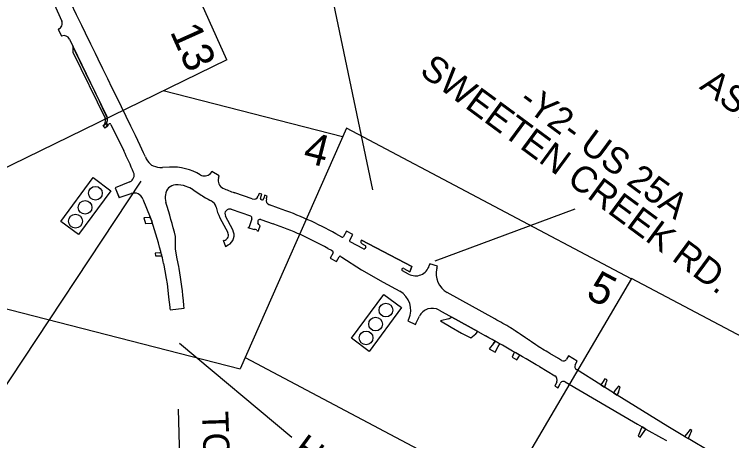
# Model space of a CAD drawing. Extents: x 945666 to 965748, y 644452 to 663300.
# Drawn here: x 951483 to 954496, y 654307 to 656097 of the extents above; entities that cross this region are included whole.
import ezdxf

# ---------------------------------------------------------------- set-up
doc = ezdxf.new("R2010")
doc.units = 0
for name, color, linetype in [('Old_Level_23', 7, 'Continuous'), ('Prop EOT', 7, 'Continuous'), ('Prop PHM Traffic Signal CELL', 7, 'Continuous'), ('Prop Shade Light', 7, 'Continuous'), ('Sheet Plan Layout CELL', 7, 'Continuous')]:
    doc.layers.add(name, color=color, linetype=linetype)

msp = doc.modelspace()

# ---------------------------------------------------------------- linework, layer by layer
at = {"layer": 'Old_Level_23'}
for p, q in [((952752.1, 656484.8), (952987.9, 655359.8)), ((951372.5, 654425.5), (952015.2, 655396.2)), ((953837.5, 655278.9), (953248.6, 655060.3)), ((952647.9, 654320.5), (952176.9, 654715.4)), ((952170.9, 654438.9), (952196.4, 653446.7))]:
    msp.add_line(p, q, dxfattribs=at)
at = {"layer": 'Prop EOT'}
for p, q in [((951906, 655368.1), (951922.9, 655327.4)), ((952049, 655244.5), (952053.8, 655246.1)), ((952058.1, 655220.5), (952063.5, 655220.5)), ((952094.4, 655095.6), (952099.3, 655096.6)), ((952097.6, 655082.8), (952102.8, 655082.8)), ((953308.3, 654818.3), (953321, 654825.6)), ((953421, 654755.8), (953430.3, 654765)), ((953494.8, 654714.8), (953502, 654725.1)), ((953515.7, 654703), (953521.7, 654714)), ((953578.6, 654667.3), (953583.9, 654678.7)), ((953599.2, 654655.5), (953605.6, 654666.2)), ((953952.8, 654552.1), (953946.2, 654541.5)), ((953966.4, 654543.6), (953961.8, 654531.7)), ((954006.3, 654518.8), (953998.9, 654508.7)), ((954019.9, 654510.3), (954015.3, 654498.4)), ((954113.8, 654353.8), (954119.5, 654364.9)), ((954127.8, 654345.9), (954135.3, 654356)), ((954306, 654334.6), (954298, 654324.8)), ((954318.9, 654327), (954313.3, 654315.9))]:
    msp.add_line(p, q, dxfattribs=at)
msp.add_lwpolyline([(952940.5, 655149), (953153.1, 655038), (953144.2, 655016.3)], dxfattribs=at)
at = {"layer": 'Prop PHM Traffic Signal CELL'}
for p, q in [((951678.6, 655227.4), (951814.6, 655411.7)), ((951814.6, 655411.7), (951889, 655356.8)), ((951889, 655356.8), (951753.1, 655172.5)), ((951753.1, 655172.5), (951678.6, 655227.4)), ((952898.9, 654737.1), (953034.8, 654921.4)), ((953034.8, 654921.4), (953109.3, 654866.5)), ((953109.3, 654866.5), (952973.4, 654682.2)), ((952973.4, 654682.2), (952898.9, 654737.1))]:
    msp.add_line(p, q, dxfattribs=at)
for centre in [(951823.6, 655345.9), (951780.1, 655286.9), (951739.9, 655228.8), (953043.8, 654855.6), (953000.3, 654796.6), (952960.1, 654738.5)]:
    msp.add_circle(centre, 28.8, dxfattribs=at)
at = {"layer": 'Prop Shade Light'}
for p, q in [((951636, 656171.9), (951682, 656068.9)), ((951668.7, 656035.6), (951667, 656035)), ((951667, 656035), (951681.8, 656006)), ((951715.4, 655992.5), (951729.6, 655960.5)), ((951728.4, 655962.9), (951729.3, 655938)), ((951729.6, 655960.5), (951802.9, 655809.7)), ((951729.3, 655938), (951864, 655660.9)), ((951802.9, 655809.7), (951871.4, 655667.9)), ((951865.4, 655657.3), (951873.9, 655661.4)), ((951873.9, 655661.4), (951865.4, 655657.3)), ((951874.3, 655659.5), (951873.9, 655661.4)), ((951856, 655629.5), (951863.6, 655619.9)), ((951868.4, 655638.9), (951877.5, 655631.8)), ((951874.5, 655634.1), (951868.4, 655638.9)), ((951877.3, 655632), (951874.5, 655634.1)), ((951888.8, 655635.1), (951942.5, 655524.6)), ((952135.3, 655456), (952104.7, 655454.5)), ((952312.8, 655438), (952306.2, 655429)), ((952343.3, 655419), (952312.8, 655438)), ((952340.6, 655409.5), (952343.3, 655419)), ((951967.8, 655393.8), (951906, 655368.1)), ((951906, 655368.1), (951922.9, 655327.5)), ((951922.9, 655327.5), (951973.1, 655344.8)), ((952234.5, 655359.7), (952262, 655341.9)), ((952511.7, 655345.3), (952508.7, 655337.8)), ((952522.2, 655341.7), (952511.7, 655345.3)), ((952508.7, 655337.8), (952507.4, 655334.2)), ((952516.2, 655324.5), (952519.5, 655334)), ((952523.6, 655317.7), (952518.7, 655319.4)), ((952519.5, 655334), (952522.2, 655341.7)), ((952531.6, 655329.8), (952528.7, 655320.3)), ((952534, 655337.6), (952531.6, 655329.8)), ((952545, 655333.7), (952534, 655337.6)), ((952541.6, 655322.2), (952542.7, 655325.9)), ((952542.7, 655325.9), (952545, 655333.7)), ((952592.8, 655283.6), (952554, 655297.1)), ((952394, 655278.6), (952474.3, 655250.7)), ((952049, 655244.6), (952026.8, 655242.7)), ((952026.8, 655242.7), (952034.5, 655219)), ((952053.8, 655246.1), (952049, 655244.6)), ((952060.6, 655229.2), (952053.8, 655246.1)), ((952346.4, 655243.3), (952379.4, 655180.7)), ((952400.6, 655191.9), (952369.8, 655250.3)), ((952480.5, 655238.1), (952469.8, 655205.7)), ((952518.5, 655235.3), (952569.8, 655217.5)), ((952034.5, 655219), (952058.1, 655220.5)), ((952058.1, 655220.5), (952063.5, 655220.5)), ((952463.4, 655202.5), (952489.7, 655193.4)), ((952510, 655214.2), (952506.3, 655221.3)), ((952507.7, 655187.1), (952513.9, 655204.9)), ((952513.9, 655204.9), (952515.5, 655209.4)), ((952159.5, 655111.9), (952159.5, 655164.1)), ((952501.4, 655189.3), (952507.7, 655187.1)), ((952858.7, 655162.1), (952833.8, 655175.9)), ((952878.4, 655187.2), (952865.5, 655164)), ((952904.6, 655172.7), (952878.4, 655187.2)), ((952891.8, 655149.5), (952904.6, 655172.7)), ((952360.7, 655149.5), (952369.2, 655121.9)), ((952948.9, 655112.1), (952893.7, 655142.7)), ((952940.5, 655149), (952939.6, 655147)), ((952943.7, 655133.9), (952956.9, 655126.6)), ((952167.5, 655071), (952159.5, 655111.9)), ((952369.2, 655121.9), (952381.7, 655128.8)), ((952799.9, 655114.7), (952814.7, 655106.5)), ((952814.7, 655106.5), (952820.5, 655102.6)), ((952958.8, 655119.8), (952955.7, 655114)), ((952094.4, 655095.6), (952074.4, 655094.9)), ((952074.4, 655094.9), (952076.4, 655083.4)), ((952076.4, 655083.4), (952097.6, 655082.8)), ((952099.3, 655096.6), (952094.4, 655095.6)), ((952097.6, 655082.8), (952102.8, 655082.8)), ((952102.8, 655082.8), (952102.8, 655082.8)), ((952822.1, 655096), (952809.4, 655073.9)), ((952809.4, 655073.9), (952835.4, 655059)), ((952835.4, 655059), (952847, 655079)), ((952854.1, 655080.7), (952858.1, 655078)), ((952858.1, 655078), (952940.5, 655024.1)), ((952173.4, 655038.5), (952167.5, 655071)), ((953227.8, 655049.9), (953225.5, 655042.2)), ((953260.4, 655040.4), (953227.8, 655049.9)), ((952940.5, 655024.1), (953032.1, 654973.3)), ((953138.9, 655006.7), (953113, 655021)), ((953118.4, 655030.6), (953144.2, 655016.3)), ((953257.9, 655030.9), (953260.4, 655040.4)), ((953032.1, 654973.3), (953101.5, 654934.8)), ((953500.9, 654818.5), (953301.2, 654929.2)), ((952137, 654856.8), (952196.8, 654862.9)), ((953139.1, 654817.4), (953135.7, 654810.1)), ((953135.7, 654810.1), (953167.4, 654795.1)), ((953167.4, 654795.1), (953170.9, 654802.5)), ((953170.9, 654802.5), (953184.3, 654829.6)), ((953308.3, 654818.4), (953272.6, 654810.2)), ((953272.6, 654810.2), (953318.3, 654783.6)), ((953321, 654825.6), (953308.3, 654818.4)), ((953430.3, 654765), (953321, 654825.6)), ((953318.3, 654783.6), (953361.3, 654758)), ((953361.3, 654758), (953400.5, 654739.1)), ((953400.5, 654739.1), (953421, 654755.9)), ((953421, 654755.9), (953430.3, 654765)), ((953494.8, 654714.8), (953476.6, 654692.6)), ((953502, 654725.1), (953494.8, 654714.8)), ((953515.7, 654703), (953521.7, 654714)), ((953476.6, 654692.6), (953502, 654678.3)), ((953502, 654678.3), (953515.7, 654703)), ((953578.6, 654667.3), (953573.4, 654657.9)), ((953573.4, 654657.9), (953594, 654646.1)), ((953583.8, 654678.7), (953578.6, 654667.3)), ((953594, 654646.1), (953599.2, 654655.5)), ((953599.2, 654655.5), (953605.6, 654666.3)), ((953732.5, 654673.3), (953723.9, 654678.3)), ((953769.1, 654651.8), (953732.5, 654673.3)), ((953781.6, 654644), (953769.1, 654651.8)), ((953810.3, 654662.9), (953802.5, 654649.3)), ((953846.4, 654640.5), (953810.3, 654662.9)), ((953838.3, 654625.2), (953846.4, 654640.5)), ((953688.4, 654618), (953753, 654580)), ((953963.3, 654566.6), (953952.8, 654552.1)), ((953972.8, 654562.8), (953963.3, 654566.6)), ((953966.4, 654543.7), (953972.8, 654562.8)), ((953761.2, 654554.7), (953753, 654536.3)), ((953753, 654536.3), (953760.4, 654533)), ((953760.4, 654533), (953767.7, 654529.8)), ((953767.7, 654529.8), (953775.4, 654547.4)), ((953796.8, 654554.3), (954099.9, 654375.9)), ((953952.8, 654552.1), (953946.2, 654541.5)), ((953946.2, 654541.5), (953961.8, 654531.8)), ((953961.8, 654531.8), (953966.4, 654543.7)), ((954020.8, 654536.7), (954006.3, 654518.8)), ((954019.9, 654510.3), (954027.7, 654533.7)), ((954027.7, 654533.7), (954020.8, 654536.7)), ((954006.3, 654518.8), (953998.9, 654508.7)), ((953998.9, 654508.7), (954015.3, 654498.5)), ((954015.3, 654498.5), (954019.9, 654510.3)), ((954099.9, 654375.9), (954119.5, 654364.9)), ((954113.8, 654353.8), (954102.7, 654326.5)), ((954119.5, 654364.9), (954113.8, 654353.8)), ((954135.3, 654356.1), (954119.5, 654364.9)), ((954127.8, 654346), (954135.3, 654356.1)), ((954102.7, 654326.5), (954110.9, 654321.7)), ((954110.9, 654321.7), (954127.8, 654346)), ((954306, 654334.7), (954298, 654324.8)), ((954298, 654324.8), (954313.3, 654315.9)), ((954313.3, 654315.9), (954318.9, 654327.1))]:
    msp.add_line(p, q, dxfattribs=at)
for points in [[(951781.9, 656018), (951766.2, 656050.3), (951744.2, 656095.3), (951720.1, 656145.4), (951681.2, 656224.3), (951657.7, 656273), (951645.7, 656297.5)], [(951823.7, 655932.1), (951804.5, 655971.9), (951781.9, 656018)], [(951759.5, 655898.7), (951743.2, 655932.2), (951732.3, 655954.6), (951729.6, 655960.5), (951728.4, 655962.9)], [(952033.3, 655498.4), (952025.7, 655515.1), (952010.9, 655546.9), (951991.5, 655587.8), (951972.1, 655627.3), (951952.5, 655667.7), (951932.7, 655709.3), (951913, 655748.8), (951894.4, 655786.8), (951875.1, 655826.5), (951855, 655867.7), (951835, 655908.9), (951823.7, 655932.1)], [(951802.9, 655809.7), (951783.1, 655850.3), (951778.9, 655858.9), (951777.5, 655861.7), (951773.2, 655870.4), (951759.5, 655898.7)], [(951871.4, 655667.9), (951869.1, 655672.7), (951859.4, 655692.7), (951840.3, 655732.3), (951820.7, 655772.9), (951802.9, 655809.7)], [(951867.3, 655623.3), (951867.5, 655623)], [(951867.5, 655623), (951872.7, 655627.1), (951875.5, 655629.7), (951877.3, 655632)], [(951868.4, 655638.9), (951868.4, 655638.9)], [(952482, 655322.1), (952408.8, 655347.5), (952408.8, 655347.5), (952407.6, 655347.9)], [(952407.6, 655347.9), (952407.6, 655347.9)], [(952023.2, 655321.9), (952053.8, 655246.1), (952060.6, 655229.2)], [(952063.5, 655220.5), (952063.5, 655220.5)], [(952463.4, 655202.5), (952463.4, 655202.5)], [(953144.2, 655016.3), (953153.1, 655038), (952940.5, 655149)], [(952102.8, 655082.8), (952102.8, 655082.8)], [(952110.1, 655051.4), (952111.4, 655044.7), (952115.7, 655020.7), (952120.9, 654988.8)], [(952193.4, 654895.2), (952191, 654916.6), (952188.8, 654935.7), (952186.5, 654954.1), (952180.9, 654993.5), (952174.8, 655030.6), (952173.4, 655038.5)], [(952120.9, 654988.8), (952124.3, 654965.4), (952127.4, 654939.5), (952131.2, 654910.1), (952133.6, 654888.2), (952135.8, 654868.4), (952136, 654865.3), (952136.5, 654862.1), (952137, 654856.8)], [(952196.8, 654862.9), (952195.5, 654875.3), (952193.4, 654895.2)], [(953267.1, 654855.5), (953321, 654825.6), (953430.3, 654765), (953461.6, 654747.6)], [(954227.6, 654366.3), (954015.3, 654498.5), (953998.9, 654508.7), (953961.8, 654531.8), (953946.2, 654541.5), (953843.6, 654605.4)], [(954119.5, 654364.9), (954135.3, 654356.1), (954200.8, 654319.4), (954222.3, 654307.4)], [(954623.6, 654133.3), (954421.9, 654252), (954406.4, 654261.1), (954313.3, 654315.9), (954298, 654324.8), (954227.6, 654366.3)], [(954318.9, 654327.1), (954328.7, 654349.5), (954321.3, 654353.6), (954306, 654334.7)]]:
    msp.add_lwpolyline(points, dxfattribs=at)
for centre, radius, start, end in [((951659.2, 656058.7), 25, 292.3217, 24.0909), ((951691.6, 655981.9), 26, 23.9453, 112.1499), ((951841.5, 655649.9), 25, 305.3243, 17.1428), ((951841.5, 655649.9), 25, 17.1428, 25.9325), ((951849.3, 655655.6), 25.3, 318.8171, 29.3178), ((951849.3, 655655.6), 25.3, 29.2276, 29.3178), ((951849.3, 655655.6), 25.3, 345.2315, 8.9433), ((951840.1, 655649.2), 37.6, 308.6221, 336.2991), ((951840.1, 655649.2), 37.6, 316.3257, 336.2991), ((951849.3, 655655.6), 25.3, 318.8171, 319.781), ((951844.6, 655657.3), 41.6, 322.3103, 328.4923), ((951884.3, 655632.9), 5, 25.9327, 148.4923), ((950261.8, 654707.3), 1868.9, 22.8539, 25.9327), ((952124.2, 655540), 100, 204.5323, 225.3117), ((952078.5, 655493.8), 35, 225.3117, 249.0253), ((952101.8, 655554.4), 100, 249.0253, 271.6452), ((952144.8, 655221.2), 235, 59.5369, 92.3285), ((951956.3, 655421.5), 30, 292.54, 22.8539), ((952281.7, 655453.9), 35, 239.5369, 314.5158), ((952374.1, 655399.4), 35, 163.226, 244.7668), ((952162.3, 655336.2), 45, 93.002, 175.1414), ((952166.2, 655261.3), 120, 71.3136, 93.002), ((952144.8, 655221.2), 165, 57.0814, 68.7466), ((951986.1, 655306.9), 40, 21.9932, 108.9966), ((952574.4, 655824.6), 505, 244.7668, 250.713), ((952237, 655329.8), 120, 175.1414, 190.5694), ((952574.4, 655824.6), 575, 237.0814, 242.5873), ((952488.6, 655341), 20, 250.85, 340.2328), ((952520, 655323.2), 4, 160.9125, 250.85), ((952524.9, 655321.5), 4, 250.85, 342.8101), ((952560.6, 655316), 20, 161.7571, 250.85), ((950261.8, 654707.3), 1951.9, 13.536, 17.9187), ((952291.3, 655278.6), 40, 12.2235, 62.5873), ((952498.5, 655323.5), 172, 192.2235, 207.8093), ((952387.5, 655259.7), 20, 70.85, 207.8093), ((952089.3, 653833.6), 1535, 60.9833, 70.85), ((950283, 654638.4), 1873.2, 13.723, 18.3831), ((950283, 654638.4), 1873.2, 18.1036, 18.3831), ((952471, 655241.2), 10, 341.7238, 70.85), ((952515.2, 655225.9), 10, 70.85, 207.4729), ((952465.1, 655207.2), 5, 250.7829, 341.7238), ((952493.9, 655186.6), 8, 19.776, 121.924), ((952518.8, 655218.9), 10, 207.4729, 250.4692), ((952089.3, 653833.6), 1465, 60.9833, 70.85), ((952359, 655170), 23, 293.3287, 27.8093), ((952359, 655170), 47, 298.8358, 27.8093), ((952861.1, 655166.5), 5, 240.9833, 330.8246), ((952365, 655156.2), 8, 237.4086, 293.3287), ((952896.1, 655147.1), 5, 150.9833, 240.9833), ((952948.5, 655142.6), 10, 154.0037, 240.9833), ((952951.3, 655116.5), 5, 240.9833, 330.9833), ((952954.5, 655122.2), 5, 330.9833, 60.9833), ((950283, 654638.4), 1873.2, 13.723, 14.1587), ((950283, 654638.4), 1873.2, 12.7359, 13.7229), ((952817.8, 655098.5), 5, 329.9283, 56.7892), ((952851.3, 655076.5), 5, 56.7892, 149.9283), ((953115.7, 655025.8), 5.5, 60.9833, 240.9833), ((953168, 655059.2), 60, 240.9833, 343.6093), ((953344.9, 655007.9), 90, 165.2281, 240.9833), ((953057.9, 654856.1), 90, 334.5523, 60.9833), ((953238, 654803), 60, 60.9833, 153.6981), ((948482.4, 645771.1), 10346, 60.55899, 60.98333), ((948482.4, 645771.1), 10265, 59.525, 60.98333), ((948482.4, 645771.1), 10265, 60.5988, 60.72501), ((948482.4, 645771.1), 10335, 59.525, 59.72459), ((948482.4, 645771.1), 10265, 60.06021, 60.19995), ((953789.5, 654656.7), 15, 238.0929, 330.233), ((953851.5, 654618.1), 15, 151.8521, 238.0929), ((953742.9, 654562.8), 20, 336.1833, 59.525), ((953789.2, 654541.3), 15, 59.525, 156.1833)]:
    msp.add_arc(centre, radius, start, end, dxfattribs=at)
for points in [[(951868.6, 655639.2), (951869.5, 655640.4), (951870.3, 655641.6), (951871.7, 655644), (951872.9, 655646.5), (951873.4, 655647.8), (951873.8, 655649.1)], [(951873.9, 655661.4), (951873.2, 655663.4), (951871.4, 655667.9)], [(951856, 655629.5), (951857.6, 655630.4), (951858.4, 655630.9), (951859.2, 655631.3), (951860.3, 655631.9), (951861.4, 655632.6), (951862.4, 655633.2), (951863.5, 655634), (951864.2, 655634.5), (951864.8, 655635), (951866.1, 655636.2), (951867.2, 655637.5), (951868.4, 655638.8), (951868.4, 655638.9)], [(951868.4, 655638.9), (951868.4, 655638.8), (951867.2, 655637.5), (951866.1, 655636.2), (951864.8, 655635), (951864.2, 655634.5), (951863.5, 655634), (951862.4, 655633.2), (951861.4, 655632.6), (951860.3, 655631.9), (951859.2, 655631.3), (951858.4, 655630.9), (951857.6, 655630.4), (951856, 655629.5)], [(953581.7, 654771.8), (953581.3, 654772), (953580.8, 654772.4), (953580.2, 654772.8), (953579.6, 654773.1), (953579.1, 654773.5), (953578.5, 654773.9), (953577.9, 654774.3), (953577.4, 654774.7), (953576.8, 654775), (953576.2, 654775.4), (953575.7, 654775.8), (953575.1, 654776.2), (953574.5, 654776.5), (953574, 654776.9), (953573.4, 654777.3), (953572.8, 654777.7), (953572.3, 654778), (953571.7, 654778.4), (953571.1, 654778.8), (953570.6, 654779.2), (953570, 654779.6), (953569.4, 654779.9), (953568.9, 654780.3), (953568.3, 654780.7), (953567.7, 654781.1)], [(953595.7, 654762.4), (953595.5, 654762.6), (953594.9, 654762.9), (953594.3, 654763.3), (953593.8, 654763.7), (953593.2, 654764.1), (953592.6, 654764.5), (953592.1, 654764.8), (953591.5, 654765.2), (953590.9, 654765.6), (953590.4, 654766), (953589.8, 654766.3), (953589.3, 654766.7), (953588.7, 654767.1), (953588.1, 654767.5), (953587.6, 654767.9), (953587, 654768.2), (953586.4, 654768.6), (953585.9, 654769), (953585.3, 654769.4), (953584.7, 654769.7), (953584.2, 654770.1), (953583.6, 654770.5), (953583, 654770.9), (953582.5, 654771.3), (953581.9, 654771.6), (953581.7, 654771.8)], [(953609.6, 654753.1), (953609, 654753.5), (953608.5, 654753.8), (953607.9, 654754.2), (953607.3, 654754.6), (953606.8, 654755), (953606.2, 654755.4), (953605.6, 654755.7), (953605.1, 654756.1), (953604.5, 654756.5), (953603.9, 654756.9), (953603.4, 654757.3), (953602.8, 654757.6), (953602.3, 654758), (953601.7, 654758.4), (953601.1, 654758.8), (953600.6, 654759.2), (953600, 654759.5), (953599.4, 654759.9), (953598.9, 654760.3), (953598.3, 654760.7), (953597.7, 654761), (953597.2, 654761.4), (953596.6, 654761.8), (953596, 654762.2), (953595.7, 654762.4)], [(953623.5, 654743.7), (953623.1, 654744), (953622.6, 654744.4), (953622, 654744.7), (953621.4, 654745.1), (953620.9, 654745.5), (953620.3, 654745.9), (953619.8, 654746.3), (953619.2, 654746.6), (953618.6, 654747), (953618.1, 654747.4), (953617.5, 654747.8), (953616.9, 654748.2), (953616.4, 654748.5), (953615.8, 654748.9), (953615.2, 654749.3), (953614.7, 654749.7), (953614.1, 654750.1), (953613.5, 654750.4), (953613, 654750.8), (953612.4, 654751.2), (953611.9, 654751.6), (953611.3, 654751.9), (953610.7, 654752.3), (953610.2, 654752.7), (953609.6, 654753.1)], [(953637.4, 654734.3), (953637.2, 654734.5), (953636.7, 654734.8), (953636.1, 654735.2), (953635.5, 654735.6), (953635, 654736), (953634.4, 654736.4), (953633.9, 654736.7), (953633.3, 654737.1), (953632.7, 654737.5), (953632.2, 654737.9), (953631.6, 654738.3), (953631, 654738.6), (953630.5, 654739), (953629.9, 654739.4), (953629.3, 654739.8), (953628.8, 654740.2), (953628.2, 654740.5), (953627.7, 654740.9), (953627.1, 654741.3), (953626.5, 654741.7), (953626, 654742.1), (953625.4, 654742.5), (953624.8, 654742.8), (953624.3, 654743.2), (953623.7, 654743.6), (953623.5, 654743.7)], [(953651.3, 654724.9), (953650.7, 654725.3), (953650.2, 654725.7), (953649.6, 654726.1), (953649.1, 654726.4), (953648.5, 654726.8), (953647.9, 654727.2), (953647.4, 654727.6), (953646.8, 654728), (953646.2, 654728.4), (953645.7, 654728.7), (953645.1, 654729.1), (953644.6, 654729.5), (953644, 654729.9), (953643.4, 654730.3), (953642.9, 654730.6), (953642.3, 654731), (953641.7, 654731.4), (953641.2, 654731.8), (953640.6, 654732.2), (953640, 654732.6), (953639.5, 654732.9), (953638.9, 654733.3), (953638.4, 654733.7), (953637.8, 654734.1), (953637.4, 654734.3)], [(953665.2, 654715.5), (953664.8, 654715.7), (953664.2, 654716.1), (953663.7, 654716.5), (953663.1, 654716.9), (953662.6, 654717.3), (953662, 654717.7), (953661.4, 654718), (953660.9, 654718.4), (953660.3, 654718.8), (953659.7, 654719.2), (953659.2, 654719.6), (953658.6, 654719.9), (953658.1, 654720.3), (953657.5, 654720.7), (953656.9, 654721.1), (953656.4, 654721.5), (953655.8, 654721.9), (953655.2, 654722.2), (953654.7, 654722.6), (953654.1, 654723), (953653.6, 654723.4), (953653, 654723.8), (953652.4, 654724.2), (953651.9, 654724.5), (953651.3, 654724.9)], [(953679, 654706), (953678.8, 654706.2), (953678.3, 654706.5), (953677.7, 654706.9), (953677.2, 654707.3), (953676.6, 654707.7), (953676, 654708.1), (953675.5, 654708.5), (953674.9, 654708.8), (953674.3, 654709.2), (953673.8, 654709.6), (953673.2, 654710), (953672.7, 654710.4), (953672.1, 654710.8), (953671.5, 654711.1), (953671, 654711.5), (953670.4, 654711.9), (953669.9, 654712.3), (953669.3, 654712.7), (953668.7, 654713.1), (953668.2, 654713.4), (953667.6, 654713.8), (953667, 654714.2), (953666.5, 654714.6), (953665.9, 654715), (953665.4, 654715.4), (953665.2, 654715.5)], [(953692.9, 654696.6), (953691.7, 654697.3), (953691.2, 654697.7), (953690.6, 654698.1), (953690.1, 654698.5), (953689.5, 654698.9), (953688.9, 654699.2), (953688.4, 654699.6), (953687.8, 654700), (953687.3, 654700.4), (953686.7, 654700.8), (953686.1, 654701.2), (953685.6, 654701.6), (953685, 654701.9), (953684.4, 654702.3), (953683.9, 654702.7), (953683.3, 654703.1), (953682.8, 654703.5), (953682.2, 654703.9), (953681.6, 654704.2), (953681.1, 654704.6), (953680.5, 654705), (953680, 654705.4), (953679.4, 654705.8), (953679, 654706)]]:
    msp.add_spline(points, degree=3, dxfattribs=at)
at = {"layer": 'Sheet Plan Layout CELL'}
for p, q in [((952375.8, 655905.5), (951841.4, 657099.2)), ((952375.8, 655905.5), (951349.9, 655406.6)), ((952861.8, 655583.3), (952108.8, 655775.6)), ((952877.5, 655619), (952431.8, 654609.4)), ((954074.1, 654987.2), (952877.5, 655619)), ((954074.6, 654988.1), (953541, 654081.3)), ((955210.6, 654388.3), (954074.6, 654988.1)), ((951224.9, 654917.7), (952431.8, 654609.4)), ((952452.4, 654656.1), (953541, 654081.3))]:
    msp.add_line(p, q, dxfattribs=at)

# ---------------------------------------------------------------- texts
at = {"layer": 'Old_Level_23'}
for s, rotation, p in [('SWEETEN CREEK RD.', 323.5908, (953180.4, 655848.7)), ('ASHEVILLE CITY', 323.5908, (954356.3, 655787.7)), ('-Y2- US 25A', 323.5908, (953595.2, 655722)), ('TO HENDERSONVILLE', 271.8558, (952271.6, 654429.2)), ('HENDERSONVILLE RD.', 323.5908, (952644.5, 654252.6))]:
    msp.add_text(s, height=110, rotation=rotation, dxfattribs=at).set_placement(p)
at = {"layer": 'Sheet Plan Layout CELL'}
for s, height, rotation, p in [('13', 131.25, 294.1148, (952135.2, 656024.7)), ('4', 131.3, 345.67, (952690.7, 655479.1)), ('5', 131.3, 332.1644, (953878, 654910.5))]:
    msp.add_text(s, height=height, rotation=rotation, dxfattribs=at).set_placement(p)

doc.saveas('drawing.dxf')
